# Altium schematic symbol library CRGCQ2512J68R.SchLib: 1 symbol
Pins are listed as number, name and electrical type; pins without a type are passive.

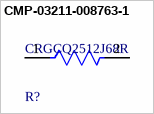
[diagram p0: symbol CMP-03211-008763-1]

## CMP-03211-008763-1
designator R?, comment CRGCQ2512J68R
CRGCQ2512 68Ω 1W ±200ppm/°C 5%200V; Manufacturer: TE Connectivity; Tolerance: 0.05; Voltage Rating: 200V; Automotive Grade: Grade 0
footprint FP-CRGCQ2512-IPC_C
footprint FP-CRGCQ2512-IPC_B
footprint FP-CRGCQ2512-IPC_A
pins: 1, 2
